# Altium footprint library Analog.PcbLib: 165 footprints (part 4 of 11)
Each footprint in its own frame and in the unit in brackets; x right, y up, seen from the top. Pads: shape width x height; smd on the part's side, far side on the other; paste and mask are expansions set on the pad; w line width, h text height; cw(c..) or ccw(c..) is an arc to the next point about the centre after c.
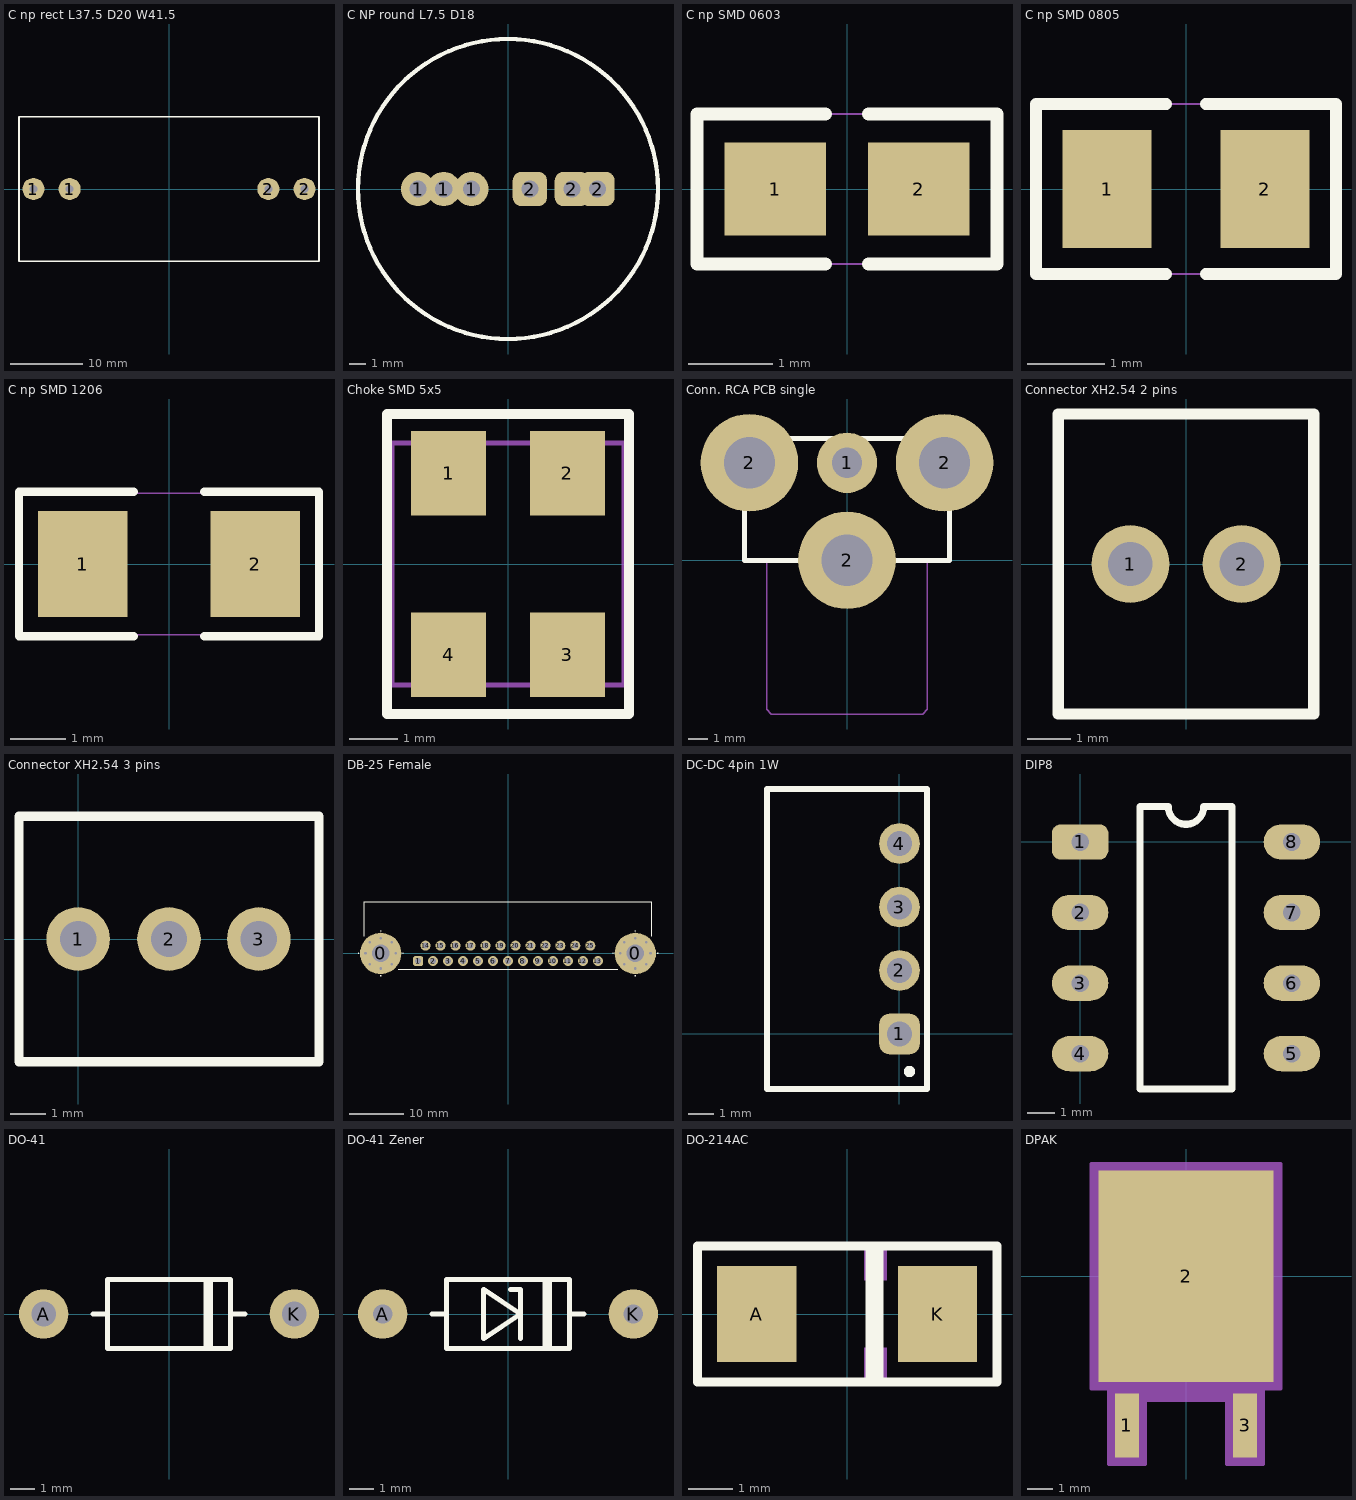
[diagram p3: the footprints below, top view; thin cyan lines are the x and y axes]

## C np rect L37.5 D20 W41.5 [mil] "MKP1J042207G"
height 1220.47
pads (4):
  round 120 hole 45: 1(-738.19,0) 1(-541.34,0) 2(541.34,0) 2(738.19,0)
Top Overlay:
  lines w10: -816.93,-393.7 -816.93,393.7 816.93,393.7 816.93,-393.7 -816.93,-393.7

## C NP round L7.5 D18 [mil]
height 800
pads (6):
  round 80 hole 40: 1(-210,0) 1(-150,0) 1(-85,0)
  rrect50% 80x80 hole 40: 2(51,0) 2(149,0) 2(209,0)
Top Overlay:
  circle w10: c0,0 r350

## C np SMD 0603 [mm]
pads (2):
  rect 1.2x1.1 smd: 1(-0.85,0) 2(0.85,0)
Top Overlay:
  lines w0.152: -0.254,-0.889 -1.778,-0.889 -1.778,0.889 -0.254,0.889 ; 0.254,-0.889 1.778,-0.889 1.778,0.889 0.254,0.889
Mechanical 13:
  lines w0.025: -1.778,-0.889 -1.778,0.889 1.778,0.889 1.778,-0.889 -1.778,-0.889
  text ".Designator" at -1.524,-0.381 h0.89

## C np SMD 0805 [mil]
pads (2):
  rect 45x60 smd: 1(-40,0) 2(40,0)
Top Overlay:
  lines w6: -10,-43 -76,-43 -76,43 -10,43 ; 10,-43 76,-43 76,43 10,43
Mechanical 13:
  lines w1: -76,-43 -76,43 76,43 76,-43 -76,-43
  text ".Designator" at -70,-20 h40

## C np SMD 1206 [mil]
pads (2):
  rect 63x75 smd: 1(-61,0) 2(61,0)
Top Overlay:
  lines w6: -25,-51 -106,-51 -106,51 -25,51 ; 25,-51 106,-51 106,51 25,51
Mechanical 13:
  lines w1: -105,-50 -105,50 105,50 105,-50 -105,-50
  text ".Designator" at -95,-20 h40

## Choke SMD 5x5 [mm]
pads (4):
  rect 1.55x1.75 smd: 1(-1.225,1.875) 2(1.225,1.875) 3(1.225,-1.875) 4(-1.225,-1.875)
Top Overlay:
  lines w0.2: -2.5,-3.1 2.5,-3.1 2.5,3.1 -2.5,3.1 -2.5,-3.1
Mechanical 13:
  lines w0.1: -2.4,-2.5 2.4,-2.5 2.4,2.5 -2.4,2.5 -2.4,-2.5
  text ".Designator" at -2.124,-0.481 h0.89

## Conn. RCA PCB single [mil]
height 464.96
pads (4):
  round 124 hole 62: 1(0,200)
  round 200 hole 105: 2(-200,200) 2(0,0) 2(200,200)
Top Overlay:
  lines w10: -210,0 -210,250 210,250 210,0 -210,0
Mechanical 13:
  lines w3: -165,0 -165,-305 -155,-315 155,-315 165,-305 165,0

## Connector XH2.54 2 pins [mil]
height 280
pads (2):
  round 70 hole 40: 1(-50,0) 2(50,0)
Top Overlay:
  lines w10: -115,-135 115,-135 115,135 -115,135 -115,-135

## Connector XH2.54 3 pins [mil]
height 280
pads (3):
  round 70 hole 40: 1(0,0) 2(100,0) 3(198.82,0)
Top Overlay:
  lines w10: -65,-135 -65,135 265,135 265,-135 -65,-135

## DB-25 Female [mil]
height 492.13
pads (43):
  round 34 hole 20: 0(-1036,0) 0(-1006,-80) 0(-1006,80) 0(-926,-110) 0(-926,110) 0(-846,-80) 0(-846,80) 0(-816,0) 0(816,0) 0(846,-80) 0(846,80) 0(926,-110) 0(926,110) 0(1006,-80) 0(1006,80) 0(1036,0)
  round 300 hole 126: 0(-926,0) 0(926,0)
  rrect50% 73x73 hole 43: 1(-654,-56)
  round 73 hole 43: 2(-545,-56) 3(-436,-56) 4(-327,-56) 5(-218,-56) 6(-109,-56) 7(0,-56) 8(109,-56) 9(218,-56) 10(327,-56) 11(436,-56) 12(545,-56) 13(654,-56) 14(-600,56) 15(-491,56) 16(-382,56) 17(-273,56) 18(-164,56) 19(-55,56) 20(54,56) 21(163,56) 22(272,56) 23(381,56) 24(490,56) 25(599,56)
Top Overlay:
  lines w7.87: -1044,124 -1044,374 ; 1044,124 1044,374
  lines w8: -1044,374 1044,374 ; -800,-115 800,-115
  lines w10: -1091,0 -1086,0 ; -926,-165 -926,-160 ; -926,160 -926,165 ; -766,0 -761,0 ; 761,0 766,0 ; 926,-165 926,-160 ; 926,160 926,165 ; 1086,0 1091,0

## DC-DC 4pin 1W [mil] "B0505S-1W"
height 400
pads (4):
  rrect50% 64x64 hole 40: 1(0,0)
  round 64 hole 40: 2(0,100) 3(0,200) 4(0,300)
Top Overlay:
  circle w10: c15.75,-59.06 r3.94
  lines w10: -208.66,-86.61 -208.66,385.83 43.31,385.83 43.31,-86.61 -208.66,-86.61

## DIP8 [mil]
pads (8):
  rrect50% 80x50 hole 25: 1(0,0)
  oval 80x50 hole 25: 2(0,-100) 3(0,-200) 4(0,-300) 5(300,-300) 6(300,-200) 7(300,-100) 8(300,0)
Top Overlay:
  lines w10: 85,-350 85,50 125,50 ccw(c150,50) 175,50 215,50 215,-350 85,-350

## DO-41 [mm]
height 2.7
pads (2):
  round 2 hole 1: A(-5.08,0) K(5.08,0)
Top Overlay:
  lines w0.2: -3.08,0 -2.5,0 ; 1.492,-1.375 1.492,1.375 ; 1.675,-1.375 1.675,1.375 ; 2.5,0 3.08,0 ; -2.5,0 -2.5,1.4 2.5,1.4 2.5,-1.4 -2.5,-1.4 -2.5,0

## DO-41 Zener [mm]
height 2.7
pads (2):
  round 2 hole 0.787: A(-5.08,0) K(5.08,0)
Top Overlay:
  lines w0.2: -3.08,0 -2.5,0 ; 0.1,1 0.5,1 0.5,-1 ; 1.492,-1.375 1.492,1.375 ; 1.675,-1.375 1.675,1.375 ; 2.5,0 3.08,0 ; -2.5,0 -2.5,1.4 2.5,1.4 2.5,-1.4 -2.5,-1.4 -2.5,0 ; -1,-1 0.5,0 -1,1 -1,-1

## DO-214AC [mil]
pads (2):
  rect 70x85 smd: A(-80,0) K(80,0)
Top Overlay:
  lines w8: 20,-59 20,60 ; 28,-60 28,60 ; -132.5,-60 -132.5,0 -132.5,60 132.5,60 132.5,-60 -132.5,-60
Mechanical 13:
  region: 15,-60 15,-30 35,-30 35,-60.04
  region: 15,60.04 15,30 35,30 35,60
  lines w1: -132.87,-60.04 -132.87,60.04 131.89,60.04 131.89,-60.04 -132.87,-60.04
  text ".Designator" at -123.03,-18.7 h40

## DPAK [mil]
pads (3):
  rect 37x98 smd paste+0 mask+0: 1(-90.16,-227.5) 3(90.16,-227.5)
  rect 267x323 smd paste+0 mask+0: 2(0,0)
Mechanical 13:
  lines w1: -17.5,-147.5 -17.5,-187.5 17.5,-187.5 17.5,-147.5 ; -132.5,-147.5 -132.5,147.5 132.5,147.5 132.5,-147.5 -132.5,-147.5 ; -107.66,-262.5 -72.66,-262.5 -72.66,-147.5 -107.66,-147.5 -107.66,-262.5 ; 72.66,-262.5 107.66,-262.5 107.66,-147.5 72.66,-147.5 72.66,-262.5
  text ".Designator" at -95,-75 h40
Mechanical 15:
  region: -117.66,-171.5 -144.5,-171.5 -144.5,171.5 144.5,171.5 144.5,-171.5 117.66,-171.5 117.66,-286.5 62.66,-286.5 62.66,-188.5 -62.66,-188.5 -62.66,-286.5 -117.66,-286.5
  lines w6: -144.5,-171.5 -117.66,-171.5 -117.66,-286.5 -62.66,-286.5 -62.66,-188.5 62.66,-188.5 62.66,-286.5 117.66,-286.5 117.66,-171.5 144.5,-171.5 144.5,171.5 -144.5,171.5 -144.5,-171.5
